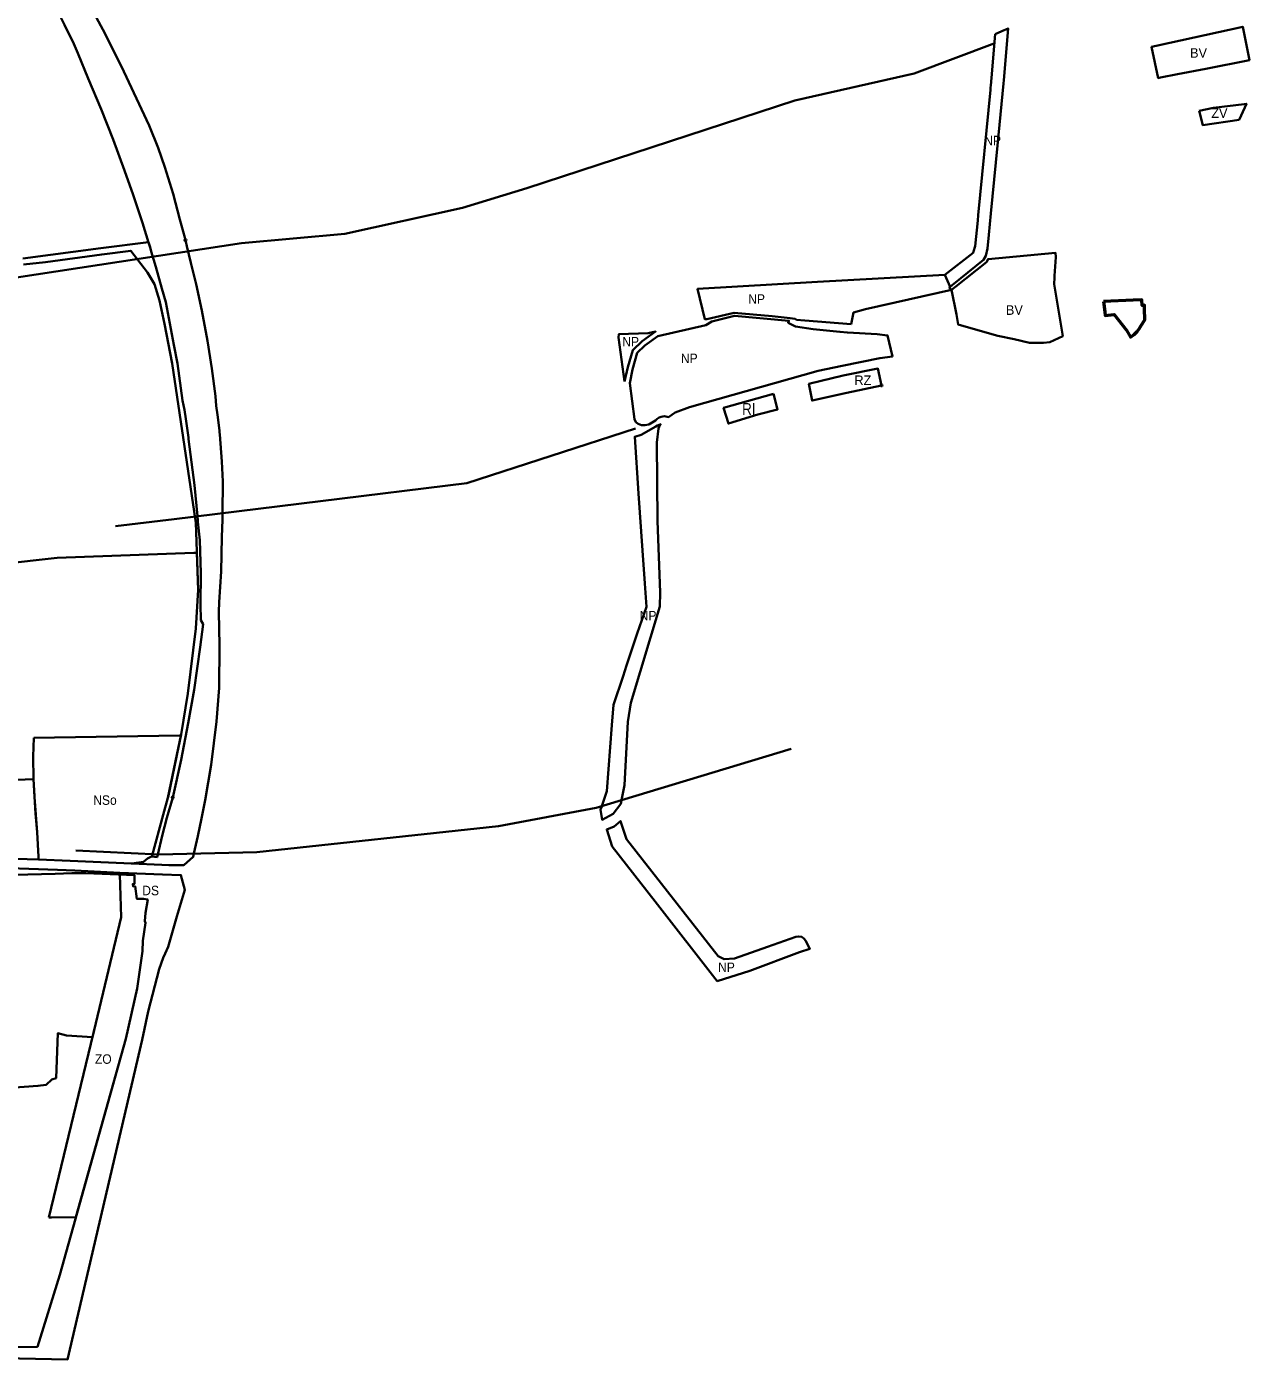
# Model space of a CAD drawing. Extents: x -650276 to -642489, y -1074311 to -1066658.
# Drawn here: x -645218 to -643674, y -1071384 to -1069701 of the extents above; entities that cross this region are included whole.
import ezdxf

# ---------------------------------------------------------------- set-up
doc = ezdxf.new("R2010")
doc.units = 0
doc.header["$LTSCALE"] = 4.8
doc.header["$PDMODE"] = 32
doc.header["$PDSIZE"] = 2.4
for name, color, linetype, lineweight in [('15', 7, 'Continuous', 35), ('24', 7, 'Continuous', 35), ('3', 7, 'Continuous', 35), ('40', 7, 'Continuous', 35), ('42', 7, 'Continuous', 35), ('46', 7, 'Continuous', 35), ('48', 7, 'Continuous', 35), ('54', 7, 'Continuous', 35), ('56', 7, 'Continuous', 35), ('6', 7, 'Continuous', 35), ('60', 7, 'Continuous', 53), ('8', 7, 'Continuous', 35)]:
    doc.layers.add(name, color=color, linetype=linetype, lineweight=lineweight)
doc.layers.add('62', color=7, linetype='Continuous')
doc.layers.add('63', color=7, linetype='Continuous')

msp = doc.modelspace()

# ---------------------------------------------------------------- linework, layer by layer
at = {"layer": '15'}
for points in [[(-645061.76, -1069981.21), (-645064.052, -1069973.429), (-645124.233, -1069980.695), (-645222.809, -1069993.701)], [(-645221.99, -1070001.66), (-645194.003, -1069998.417), (-645123.206, -1069988.629), (-645086.484, -1069984.195), (-645065.235, -1070011.695)], [(-645033.53, -1070674.55), (-645022.64, -1070626.93), (-645014.07, -1070580.72), (-645006.44, -1070538.78), (-644998.92, -1070484.58), (-644995.14, -1070455.72), (-644998.17, -1070450.59), (-644998.25, -1070430.5), (-644997.87, -1070391.16), (-644999.47, -1070349.63), (-645001.64, -1070326.4), (-645001.81, -1070324.58), (-645002.308, -1070319.268), (-645005.98, -1070280.14), (-645013.51, -1070222.04), (-645013.77, -1070220.04), (-645016.92, -1070196.32), (-645018.56, -1070184.92), (-645021.14, -1070173.07), (-645027.49, -1070126.56), (-645032.21, -1070102.73), (-645042.27, -1070049.23), (-645047.28, -1070031.83), (-645054.73, -1070004.56), (-645060.612, -1069985.022), (-645061.76, -1069981.21)], [(-645065.235, -1070011.695), (-645056.555, -1070026.163), (-645050.293, -1070047.035), (-645043.92, -1070076.344), (-645034.122, -1070126.616), (-645004.791, -1070324.889), (-645004.523, -1070326.697)], [(-645004.523, -1070326.697), (-645004.434, -1070327.302), (-645001.312, -1070412.099), (-645004.327, -1070461.264), (-645014.277, -1070543.11), (-645023.048, -1070595.033), (-645039.574, -1070675.065)], [(-645039.574, -1070675.065), (-645045.493, -1070696.321), (-645059.308, -1070747.712), (-645059.403, -1070749.195), (-645053.21, -1070749.75), (-645052.4, -1070746.427), (-645046.63, -1070722.77), (-645041, -1070700.44), (-645033.53, -1070674.55)]]:
    msp.add_lwpolyline(points, dxfattribs=at)
msp.add_point((-645033.53, -1070674.55), dxfattribs=at)
at = {"layer": '24'}
for points in [[(-645322.13, -1069447.96), (-645309.62, -1069467.79), (-645303.57, -1069480.49), (-645268.57, -1069533.23), (-645242.75, -1069570.26), (-645230.42, -1069597.39), (-645227.27, -1069602.68), (-645225.7, -1069605.32), (-645214.76, -1069622.37), (-645198.41, -1069650.49), (-645185.17, -1069673.38), (-645179.12, -1069681.3), (-645170.3, -1069698.91), (-645158.43, -1069722.61), (-645153.44, -1069734.71), (-645140.27, -1069766.68), (-645123.84, -1069805.38), (-645108.74, -1069843.58), (-645094.42, -1069882.65), (-645083.31, -1069913.37), (-645071.53, -1069948.89), (-645063.96, -1069973.73), (-645063.23, -1069976.2), (-645062.57, -1069978.46)], [(-645017.46, -1069970.61), (-645018.28, -1069967.49), (-645024.45, -1069944.43), (-645032.85, -1069912.07), (-645043.5, -1069878.37), (-645051.78, -1069854.2), (-645063.26, -1069825.99), (-645095.1, -1069757.62), (-645118.98, -1069710.08), (-645143.56, -1069664.05), (-645148.8, -1069656.1), (-645150.3, -1069653.84), (-645153.33, -1069649.24), (-645166.67, -1069629), (-645184.88, -1069596.58), (-645202.56, -1069568.23), (-645230.1, -1069525.98)], [(-645062.57, -1069978.46), (-645061.76, -1069981.21), (-645060.612, -1069985.022), (-645054.73, -1070004.56), (-645047.28, -1070031.83), (-645042.27, -1070049.23), (-645032.21, -1070102.73), (-645027.49, -1070126.56), (-645021.14, -1070173.07), (-645018.56, -1070184.92), (-645016.92, -1070196.32), (-645013.77, -1070220.04), (-645013.51, -1070222.04), (-645005.98, -1070280.14), (-645002.308, -1070319.268), (-645001.81, -1070324.58), (-645001.64, -1070326.4), (-644999.47, -1070349.63), (-644997.87, -1070391.16), (-644998.25, -1070430.5), (-644998.17, -1070450.59), (-644995.14, -1070455.72), (-644998.92, -1070484.58), (-645006.44, -1070538.78), (-645014.07, -1070580.72), (-645022.64, -1070626.93), (-645033.53, -1070674.55)], [(-644996.88, -1070059.73), (-645004.02, -1070026.44), (-645010.54, -1069999.3), (-645015.548, -1069978.177), (-645016.01, -1069976.23), (-645016.89, -1069972.82), (-645017.46, -1069970.61)], [(-645033.53, -1070674.55), (-645041, -1070700.44), (-645046.63, -1070722.77), (-645052.4, -1070746.427), (-645053.21, -1070749.75), (-645060.46, -1070749.1), (-645065.17, -1070751.39), (-645070.3, -1070755.92), (-645079.38, -1070756.91), (-645085.58, -1070758.04), (-645047.39, -1070759.71), (-645038.44, -1070759.83), (-645019.57, -1070760.07), (-645007.68, -1070749.5), (-645006.739, -1070745.384), (-645001.71, -1070723.39), (-644997.14, -1070700.88), (-644992.6, -1070677.92), (-644985.04, -1070633.43), (-644978.44, -1070578.56), (-644975.05, -1070536.16), (-644974.44, -1070482.48), (-644975.29, -1070440.14), (-644974.69, -1070427.86), (-644972.48, -1070389.15), (-644971.37, -1070345.98), (-644970.61, -1070323.44), (-644970.55, -1070321.56), (-644970.524, -1070315.358), (-644970.36, -1070275.49), (-644971.47, -1070250.14), (-644974, -1070216.2), (-644974.29, -1070213.17), (-644974.49, -1070210.98), (-644976.94, -1070191.41), (-644978.49, -1070180.05), (-644979.57, -1070167.9), (-644984.21, -1070132.81), (-644989.62, -1070097.79), (-644996.88, -1070059.73)], [(-645327.76, -1071380.76), (-645166.34, -1071384.07), (-645071.99, -1070980.72), (-645064.39, -1070944.7), (-645050.47, -1070891.48), (-645045.74, -1070877.19), (-645043, -1070871.35), (-645039.25, -1070863.33), (-645028.25, -1070824.83), (-645018.18, -1070791.34), (-645023.25, -1070772.62), (-645046.46, -1070771.98), (-645100.32, -1070769.5), (-645156.988, -1070766.884), (-645179.18, -1070765.86), (-645275.8, -1070762.66)], [(-645303, -1070774), (-645182, -1070771), (-645161, -1070770), (-645143, -1070770), (-645081.75, -1070772.79), (-645081.85, -1070781.59), (-645081.57, -1070783.53), (-645083.95, -1070783.89), (-645083.49, -1070786.92), (-645081.13, -1070786.56), (-645081.13, -1070786.56), (-645078.85, -1070802.46), (-645070.2, -1070802.33), (-645065.01, -1070803.22), (-645068.07, -1070820.37), (-645068.52, -1070830.52), (-645068.07, -1070832.72), (-645071.18, -1070855.63), (-645071.77, -1070868.73), (-645078.23, -1070915.65), (-645092.67, -1070979.52), (-645176.14, -1071277.26), (-645204.341, -1071368.19), (-645348.55, -1071370.559)]]:
    msp.add_lwpolyline(points, dxfattribs=at)
for p in [(-645017.46, -1069970.61), (-645033.53, -1070674.55)]:
    msp.add_point(p, dxfattribs=at)
at = {"layer": '3'}
for points in [[(-643791.88, -1069725.25), (-643797.75, -1069726.51), (-643789.3, -1069766.05), (-643786.35, -1069765.46), (-643764.94, -1069761.27), (-643729.34, -1069754.3), (-643674.3, -1069743.53), (-643682.61, -1069701.16)], [(-643920.84, -1070026.46), (-643920.29, -1070017.73), (-643920.16, -1070015.69), (-643918.69, -1069992.23), (-643918.88, -1069986.82), (-644004.06, -1069994.59), (-644005.92, -1069998.62), (-644044.7, -1070029.04), (-644050.12, -1070033.64), (-644044.18, -1070064.43), (-644041.71, -1070077.29), (-644022.77, -1070082.66), (-643991.99, -1070091.37), (-643971.03, -1070095.79), (-643951.99, -1070100.35), (-643933.96, -1070100.18), (-643926.33, -1070099.5), (-643909.87, -1070091.95)]]:
    msp.add_lwpolyline(points, close=True, dxfattribs=at)
at = {"layer": '40'}
for points in [[(-643737.47, -1069807.24), (-643733.02, -1069825.4), (-643687.2, -1069818.8), (-643680.15, -1069803.22), (-643678.02, -1069798.52), (-643680.83, -1069798.86), (-643719.42, -1069803.49)], [(-645442.836, -1070659.455), (-645426.34, -1070660.33), (-645209.41, -1070651.2), (-645206.7, -1070694.76), (-645204.66, -1070718.51), (-645203.13, -1070749.36), (-645202.96, -1070752.89), (-645275.236, -1070750.954), (-645282, -1070742), (-645301, -1070736), (-645324, -1070736), (-645379, -1070743), (-645415, -1070737), (-645435.711, -1070727.497)]]:
    msp.add_lwpolyline(points, close=True, dxfattribs=at)
at = {"layer": '42'}
for points in [[(-645155.777, -1071204.626), (-645092.67, -1070979.52), (-645078.23, -1070915.65), (-645071.77, -1070868.73), (-645071.18, -1070855.63), (-645068.07, -1070832.72), (-645068.52, -1070830.52), (-645068.07, -1070820.37), (-645065.01, -1070803.22), (-645070.2, -1070802.33), (-645078.85, -1070802.46), (-645081.13, -1070786.56), (-645081.13, -1070786.56), (-645083.49, -1070786.92), (-645083.95, -1070783.89), (-645081.57, -1070783.53), (-645081.85, -1070781.59), (-645081.75, -1070772.79), (-645100.268, -1070771.946)], [(-645100.268, -1070771.946), (-645098.438, -1070825.558), (-645130.749, -1070959.561)], [(-645130.749, -1070959.561), (-645130.749, -1070959.561), (-645189.902, -1071204.885)], [(-645189.902, -1071204.885), (-645186.64, -1071204.86), (-645155.777, -1071204.626)]]:
    msp.add_lwpolyline(points, dxfattribs=at)
at = {"layer": '46'}
for points in [[(-645023.048, -1070595.033), (-645014.277, -1070543.11), (-645004.327, -1070461.264), (-645001.312, -1070412.099), (-645003.03, -1070365.427), (-645003.102, -1070365.432), (-645006.86, -1070365.38), (-645179.26, -1070371.74), (-645326.62, -1070388.32), (-645414.65, -1070395.37), (-645409.38, -1070411.41), (-645408.66, -1070414.62), (-645404.34, -1070433.93), (-645404.4, -1070435.88), (-645440.61, -1070469.53), (-645451.226, -1070466.394), (-645455.09, -1070479.21), (-645458.46, -1070478.86), (-645454.02, -1070501.52), (-645448.36, -1070563), (-645449.82, -1070592.72), (-645442.834, -1070659.455)], [(-645209.41, -1070651.2), (-645209.79, -1070622.69), (-645208.96, -1070599.22)], [(-645208.96, -1070599.22), (-645025.12, -1070596.42), (-645023.346, -1070596.478), (-645023.048, -1070595.033)], [(-645442.834, -1070659.455), (-645426.34, -1070660.33), (-645209.41, -1070651.2)]]:
    msp.add_lwpolyline(points, dxfattribs=at)
at = {"layer": '48'}
for points in [[(-643995.17, -1069710.42), (-643999.94, -1069765.62), (-644000.79, -1069775.42), (-644001.04, -1069778.063), (-644001.29, -1069780.7), (-644016.47, -1069938.99), (-644017.15, -1069945.93), (-644020.26, -1069978.38), (-644022.43, -1069984.87), (-644022.99, -1069986.58), (-644058.55, -1070014.4), (-644051.913, -1070029.549), (-644049.311, -1070027.453), (-644009.95, -1069995.74), (-644006.96, -1069990.34), (-644005.06, -1069981.28), (-644003.06, -1069964.06), (-644000.52, -1069937.19), (-643992.27, -1069851.31), (-643984.845, -1069772.863), (-643984.44, -1069768.58), (-643978.85, -1069703.4), (-643986.744, -1069706.796)], [(-644381.21, -1070181.71), (-644218.65, -1070135.75), (-644188.44, -1070129.43), (-644140.72, -1070119.57), (-644125, -1070117.83), (-644130.91, -1070091.1), (-644144.13, -1070089.47), (-644181.81, -1070087.51), (-644191.26, -1070086.47), (-644225.13, -1070082.95), (-644247.3, -1070079.69), (-644256.54, -1070075.02), (-644255.52, -1070072.5), (-644324.42, -1070066.48), (-644352.71, -1070073.46), (-644360.41, -1070077.91), (-644421.26, -1070091.99), (-644437.34, -1070103.76), (-644447.13, -1070113.11), (-644453.22, -1070133.99), (-644456.41, -1070151.18), (-644450.72, -1070196.97), (-644448.76, -1070200.77), (-644445.9, -1070202.83), (-644441.8, -1070204.26), (-644437.415, -1070204.436), (-644432.53, -1070203.32), (-644424.14, -1070198.29), (-644421.88, -1070196.28), (-644419.51, -1070194.76), (-644416.67, -1070193.7), (-644412.54, -1070193.18), (-644407.55, -1070194.16), (-644399.15, -1070188.55)], [(-644463.28, -1070149.42), (-644459.09, -1070131.08), (-644452.65, -1070109.46), (-644440.64, -1070098.4), (-644423.99, -1070086.17), (-644433.19, -1070088.37), (-644470.17, -1070089.43), (-644470.55, -1070093.61)], [(-644491.691, -1070685.524), (-644491.82, -1070685.92), (-644493.5, -1070689.75), (-644491.42, -1070702.64), (-644477.46, -1070695.09), (-644467.84, -1070682.37), (-644466.998, -1070678.065), (-644463.28, -1070659.06), (-644458.85, -1070579.04), (-644455.2, -1070554.88), (-644418.69, -1070433.36), (-644418.23, -1070415.62), (-644421.45, -1070325.29), (-644422.5, -1070226.42), (-644420.14, -1070208.56), (-644418.61, -1070204.51), (-644417.36, -1070203.24), (-644421.47, -1070204.77), (-644423.66, -1070205.86), (-644442.2, -1070216.72), (-644450.15, -1070219.06), (-644445.28, -1070290.84), (-644440.36, -1070362.62), (-644437.53, -1070404.1), (-644435.51, -1070433.85), (-644447.14, -1070467.28), (-644460.5, -1070507.68), (-644464.98, -1070521.13), (-644476.94, -1070557.45), (-644479.06, -1070583.13), (-644485.64, -1070666.7), (-644488.01, -1070674.2)], [(-644346.21, -1070906.61), (-644305.07, -1070893.39), (-644242.29, -1070869.82), (-644229.12, -1070865.52), (-644234.66, -1070855.08), (-644236.3, -1070852.87), (-644239.47, -1070850.71), (-644243.15, -1070849.89), (-644246.93, -1070850.52), (-644282.77, -1070863.19), (-644324.34, -1070877.71), (-644337.15, -1070878.64), (-644344.86, -1070875.09), (-644460.82, -1070727.21), (-644465.31, -1070713.25), (-644468.1, -1070704.23), (-644476.35, -1070710.99), (-644485.61, -1070714.95), (-644478.67, -1070736.28), (-644424.37, -1070806.03)]]:
    msp.add_lwpolyline(points, close=True, dxfattribs=at)
for points in [[(-644058.55, -1070014.4), (-644219.33, -1070023.53), (-644370.87, -1070032.13), (-644361.74, -1070070.32), (-644359.02, -1070070.67), (-644324.72, -1070062.44), (-644276.85, -1070066.62), (-644254.13, -1070069.08)], [(-644177.01, -1070076.69), (-644177.01, -1070076.69), (-644174.12, -1070062.16), (-644159.02, -1070057.84), (-644050.12, -1070033.64), (-644053.18, -1070030.57), (-644051.913, -1070029.549), (-644058.55, -1070014.4)], [(-644254.13, -1070069.08), (-644254.25, -1070069.37), (-644247.72, -1070070.21), (-644245.9, -1070071.26), (-644235.49, -1070072.08), (-644177.01, -1070076.69)]]:
    msp.add_lwpolyline(points, dxfattribs=at)
at = {"layer": '54'}
for points in [[(-645230.538, -1070017.864), (-644946.741, -1069974.541), (-644816.387, -1069962.572), (-644667.646, -1069930.034), (-644586.303, -1069905.244), (-644248.286, -1069794.155), (-644097.378, -1069760.147), (-643995.653, -1069721.915)], [(-645105.781, -1070331.996), (-645031.648, -1070322.877), (-644662.188, -1070277.428), (-644449.34, -1070208.499)], [(-645155.795, -1070741.501), (-645051.039, -1070746.492), (-644927.167, -1070743.394), (-644622.134, -1070710.86), (-644498.737, -1070687.652), (-644252.543, -1070613.291)]]:
    msp.add_lwpolyline(points, dxfattribs=at)
at = {"layer": '56'}
msp.add_line((-645207.88, -1070674.2), (-645204.66, -1070718.51), dxfattribs=at)
msp.add_lwpolyline([(-645208.96, -1070599.22), (-645209.79, -1070622.69), (-645209.41, -1070651.2), (-645207.88, -1070674.2), (-645204.66, -1070718.51), (-645203.13, -1070749.36), (-645202.96, -1070752.89), (-645163.06, -1070754.64), (-645085.58, -1070758.04), (-645079.38, -1070756.91), (-645070.3, -1070755.92), (-645065.17, -1070751.39), (-645060.46, -1070749.1), (-645059.421, -1070749.039), (-645059.308, -1070747.712), (-645045.493, -1070696.321), (-645039.574, -1070675.065), (-645028.384, -1070620.876), (-645023.346, -1070596.478), (-645025.12, -1070596.42)], close=True, dxfattribs=at)
for points in [[(-645208.96, -1070599.22), (-645209.79, -1070622.69), (-645209.41, -1070651.2), (-645207.88, -1070674.2)], [(-645023.346, -1070596.478), (-645025.12, -1070596.42), (-645208.96, -1070599.22)], [(-645060.46, -1070749.1), (-645059.421, -1070749.039), (-645059.308, -1070747.712), (-645045.493, -1070696.321), (-645039.574, -1070675.065), (-645039.338, -1070673.923), (-645023.346, -1070596.478)], [(-645204.66, -1070718.51), (-645203.13, -1070749.36), (-645202.96, -1070752.89)], [(-645202.96, -1070752.89), (-645163.06, -1070754.64), (-645085.58, -1070758.04), (-645079.38, -1070756.91), (-645070.3, -1070755.92), (-645065.17, -1070751.39), (-645060.46, -1070749.1)], [(-645100.268, -1070771.946), (-645143, -1070770), (-645161, -1070770), (-645182, -1070771), (-645303, -1070774), (-645351, -1070800), (-645400.05, -1070819.84), (-645406.09, -1070822.34), (-645409.52, -1070823.76), (-645418.67, -1070827.72), (-645421.09, -1070827.89), (-645433.49, -1070828.76), (-645452.31, -1070825.52), (-645455.184, -1070825.042)], [(-645130.749, -1070959.561), (-645098.438, -1070825.558), (-645100.268, -1070771.946)], [(-645495.87, -1071017.81), (-645475.01, -1071020.72), (-645426.38, -1071032.8), (-645361.54, -1071041.54), (-645255.93, -1071042.36), (-645203.66, -1071038.81), (-645193.24, -1071037.31), (-645186.18, -1071030.83), (-645180.72, -1071028.86), (-645178.73, -1070972.35), (-645167.47, -1070975.2), (-645134.973, -1070977.077), (-645134.973, -1070977.077), (-645130.749, -1070959.561)]]:
    msp.add_lwpolyline(points, dxfattribs=at)
at = {"layer": '6'}
msp.add_lwpolyline([(-644275.05, -1070164.59), (-644338.06, -1070182.64), (-644331.9, -1070202.4), (-644295.01, -1070190.9), (-644269.84, -1070184.57)], close=True, dxfattribs=at)
at = {"layer": '60'}
msp.add_lwpolyline([(-643858.23, -1070048.35), (-643856.72, -1070061.26), (-643856.49, -1070065.66), (-643844.87, -1070064.51), (-643829.38, -1070084.37), (-643824.22, -1070093.34), (-643819.67, -1070089.82), (-643815.9, -1070086.27), (-643813.21, -1070082.8), (-643810.91, -1070078.63), (-643806.17, -1070071.18), (-643806.59, -1070057.37), (-643806.86, -1070053.03), (-643809.71, -1070053.15), (-643810, -1070046), (-643820.78, -1070046.59)], close=True, dxfattribs=at)
at = {"layer": '8'}
for p, q in [((-644138.78, -1070154.07), (-644143.31, -1070132.95)), ((-644182.31, -1070163.66), (-644138.78, -1070154.07))]:
    msp.add_line(p, q, dxfattribs=at)
msp.add_lwpolyline([(-644143.31, -1070132.95), (-644143.31, -1070132.95), (-644143.31, -1070132.95), (-644187.11, -1070141.58), (-644230.4, -1070152.08), (-644226.23, -1070173.28), (-644182.31, -1070163.66)], dxfattribs=at)
msp.add_point((-644138.78, -1070154.07), dxfattribs=at)

# ---------------------------------------------------------------- texts
at = {"layer": '62'}
for s, p in [('BV', (-643749.135, -1069740.303)), ('ZV', (-643722.385, -1069816.315)), ('BV', (-643981.639, -1070065.037)), ('RZ', (-644172.882, -1070153.612))]:
    msp.add_text(s, height=12, dxfattribs=at).set_placement(p)
for s, height, width, p in [('NP', 12, 0.95, (-644008.985, -1069850.967)), ('NP', 12, 0.95, (-644306.985, -1070050.967)), ('NP', 12, 0.95, (-644465.985, -1070104.967)), ('NP', 12, 0.95, (-644391.985, -1070125.967)), ('RI', 15, 0.85, (-644314.705, -1070191.481)), ('NP', 12, 0.95, (-644444, -1070450.967)), ('DS', 12, 0.95, (-645072.003, -1070798.001)), ('NP', 12, 0.95, (-644345, -1070894.967)), ('ZO', 12, 0.95, (-645131.758, -1071010.853))]:
    msp.add_text(s, height=height, dxfattribs=dict(at, width=width)).set_placement(p)
at = {"layer": '63', "width": 0.95}
msp.add_text('NSo', height=12, dxfattribs=at).set_placement((-645133.866, -1070683.823))

doc.saveas('drawing.dxf')
